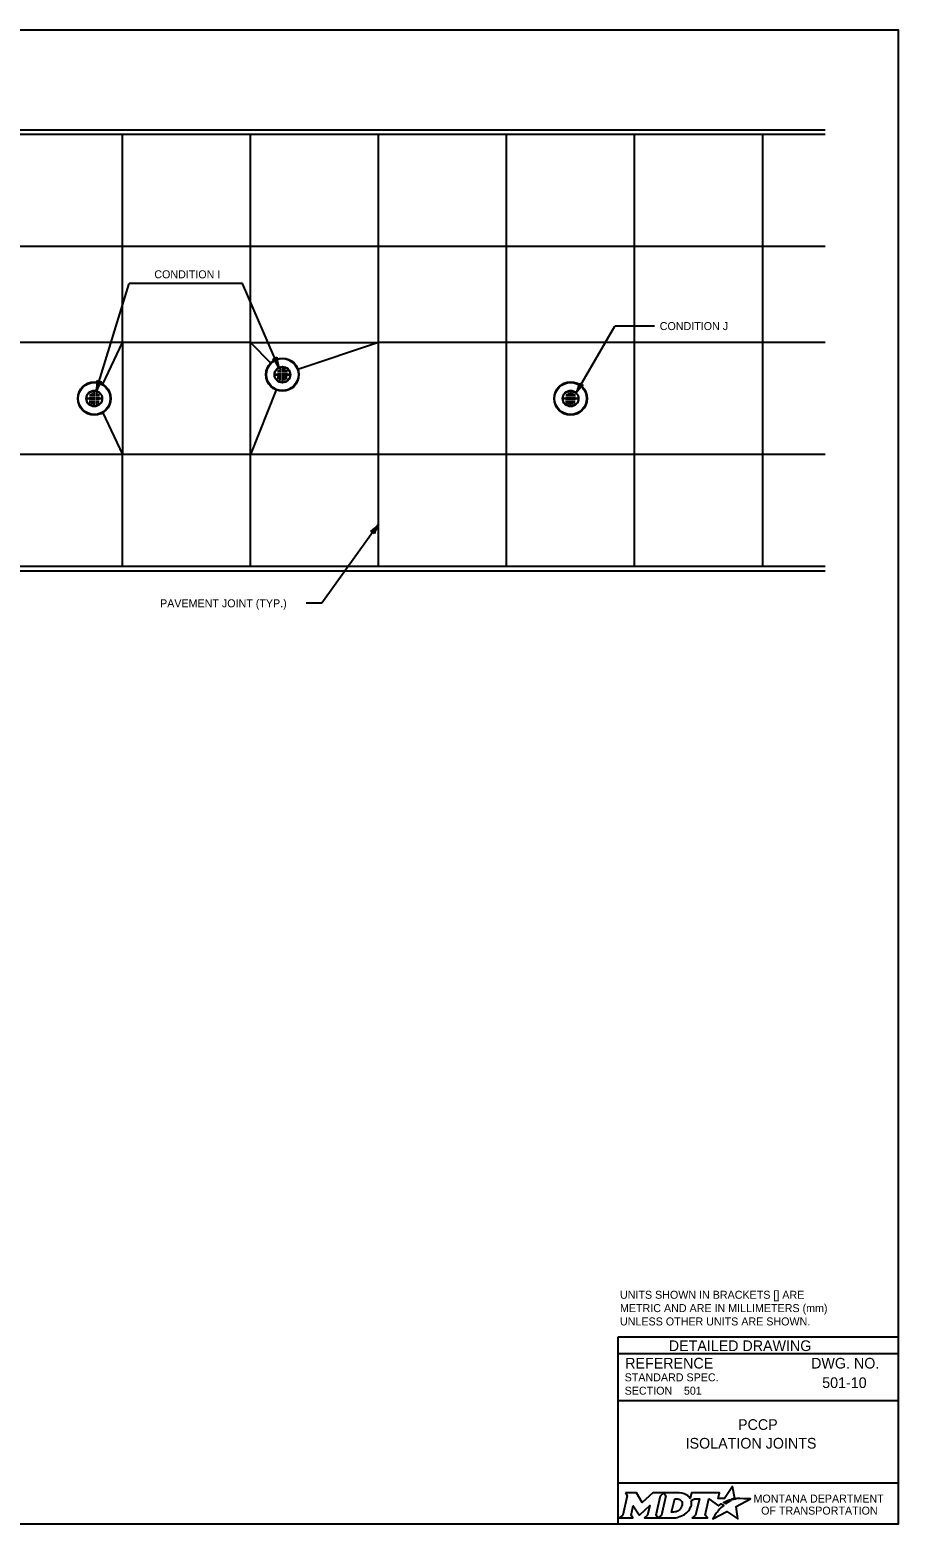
# Model space of a CAD drawing. Extents: x 49991.4 to 50029.7, y 49987.6 to 50011.4.
# Drawn here: x 50010.24 to 50016.75, y 49987.8 to 49999 of the extents above; entities that cross this region are included whole.
import ezdxf

# ---------------------------------------------------------------- set-up
doc = ezdxf.new("R2010")
doc.units = 0
for name, color, linetype in [('Default', 7, 'Continuous'), ('Level 1', 7, 'Continuous'), ('Level 2', 7, 'Continuous'), ('Level 3', 7, 'Continuous'), ('Level 5', 7, 'Continuous')]:
    doc.layers.add(name, color=color, linetype=linetype)

msp = doc.modelspace()

# ---------------------------------------------------------------- linework, layer by layer
at = {"layer": 'Default'}
for points in [[(50015.513, 49987.981), (50015.502, 49987.987), (50015.514, 49987.99), (50015.526, 49987.991), (50015.508, 49988.082), (50015.449, 49987.99), (50015.401, 49987.99), (50015.412, 49988.034), (50015.202, 49988.034), (50015.192, 49987.991), (50015.186, 49988)], [(50014.706, 49988.034), (50014.72, 49988.01), (50014.686, 49987.867), (50014.66, 49987.845), (50014.762, 49987.845), (50014.749, 49987.867), (50014.765, 49987.937), (50014.809, 49987.868), (50014.814, 49987.868), (50014.889, 49987.938), (50014.872, 49987.867), (50014.848, 49987.845), (50014.949, 49987.845), (50014.936, 49987.868), (50014.969, 49988.011)], [(50014.969, 49988.011), (50014.994, 49988.034), (50014.912, 49988.034), (50014.832, 49987.961), (50014.788, 49988.034), (50014.706, 49988.034)], [(50015.108, 49988.034), (50014.994, 49988.034), (50015.009, 49988.011), (50014.975, 49987.867), (50014.949, 49987.845), (50015.06, 49987.845)], [(50015.132, 49987.947), (50015.13, 49987.939), (50015.127, 49987.93), (50015.123, 49987.922), (50015.118, 49987.914), (50015.111, 49987.907), (50015.103, 49987.901), (50015.095, 49987.896), (50015.086, 49987.892), (50015.077, 49987.89), (50015.067, 49987.889), (50015.052, 49987.889), (50015.075, 49987.989), (50015.091, 49987.989), (50015.099, 49987.988), (50015.106, 49987.986), (50015.113, 49987.983), (50015.119, 49987.979), (50015.124, 49987.974), (50015.128, 49987.968), (50015.13, 49987.962), (50015.132, 49987.955), (50015.132, 49987.952), (50015.132, 49987.947)], [(50015.199, 49987.975), (50015.224, 49987.988), (50015.261, 49987.988), (50015.232, 49987.867), (50015.205, 49987.845), (50015.321, 49987.845), (50015.304, 49987.867), (50015.332, 49987.988), (50015.403, 49987.936), (50015.424, 49987.951), (50015.444, 49987.94)], [(50015.388, 49987.884), (50015.373, 49987.86), (50015.368, 49987.852), (50015.362, 49987.844), (50015.36, 49987.839), (50015.465, 49987.893), (50015.549, 49987.838), (50015.536, 49987.93), (50015.643, 49987.989), (50015.594, 49987.989), (50015.564, 49987.99), (50015.543, 49987.99), (50015.536, 49987.989), (50015.531, 49987.987), (50015.523, 49987.985), (50015.513, 49987.981)], [(50015.462, 49987.954), (50015.46, 49987.952), (50015.442, 49987.961), (50015.452, 49987.967), (50015.456, 49987.969), (50015.465, 49987.973), (50015.47, 49987.976), (50015.478, 49987.979), (50015.485, 49987.982), (50015.497, 49987.974), (50015.493, 49987.972), (50015.489, 49987.97), (50015.484, 49987.967), (50015.479, 49987.965), (50015.478, 49987.963), (50015.475, 49987.962), (50015.472, 49987.96), (50015.47, 49987.959), (50015.467, 49987.957), (50015.465, 49987.955), (50015.462, 49987.954)], [(50015.106, 49987.852), (50015.114, 49987.855), (50015.127, 49987.86), (50015.148, 49987.871)], [(50015.402, 49987.9), (50015.402, 49987.9)]]:
    msp.add_lwpolyline(points, dxfattribs=at)
for centre, radius, start, end in [((50015.131, 49987.955), 0.0709, 339.5329, 15.8582), ((50015.087, 49987.973), 0.118, 300.9103, 339.1383)]:
    msp.add_arc(centre, radius, start, end, dxfattribs=at)
for centre, major_axis, ratio, start_param, end_param in [((50015.106, 49987.986), (0.0834, -0.0037), 0.568097, 0.61298, 1.570796), ((50015.161, 49987.994), (0.0361, -0.0295), 0.469099, 1.225588, 1.570796), ((50015.06, 49987.993), (0, 0.148), 0.987302, 3.139398, 3.456847), ((50015.395, 49987.892), (-0.00694, -0.00806), 0.008222, 0, 3.137361), ((50015.412, 49987.911), (-0.0098, -0.0102), 0.016458, 3.141593, 6.279097), ((50015.433, 49987.93), (-0.0112, -0.0097), 0.021651, 3.157348, 6.283185)]:
    msp.add_ellipse(centre, major_axis=major_axis, ratio=ratio, start_param=start_param, end_param=end_param, dxfattribs=at)
at = {"layer": 'Level 1'}
for p, q in [((50016.203, 49998.248), (50005.815, 49998.248)), ((50016.203, 49998.216), (50005.815, 49998.216)), ((50010.935, 49996.656), (50010.935, 49998.216)), ((50011.895, 49996.656), (50011.895, 49998.216)), ((50012.855, 49997.376), (50012.855, 49998.216)), ((50013.815, 49994.976), (50013.815, 49998.216)), ((50014.775, 49994.976), (50014.775, 49998.216)), ((50015.735, 49994.976), (50015.735, 49998.216)), ((50016.203, 49997.376), (50000.003, 49997.376)), ((50012.855, 49994.976), (50012.855, 49997.376)), ((50011.895, 49996.656), (50000.003, 49996.656)), ((50010.787, 49996.343), (50010.935, 49996.656)), ((50010.935, 49996.656), (50010.935, 49995.816)), ((50011.895, 49996.656), (50012.046, 49996.503)), ((50011.895, 49995.816), (50011.895, 49996.656)), ((50011.895, 49996.656), (50012.855, 49996.656)), ((50012.855, 49996.656), (50012.251, 49996.454)), ((50016.203, 49996.656), (50012.855, 49996.656)), ((50012.118, 49996.46), (50012.118, 49996.43)), ((50012.134, 49996.463), (50012.134, 49996.43)), ((50012.149, 49996.46), (50012.149, 49996.43)), ((50012.088, 49996.423), (50012.088, 49996.407)), ((50012.103, 49996.451), (50012.103, 49996.43)), ((50012.103, 49996.426), (50012.103, 49996.404)), ((50012.103, 49996.379), (50012.103, 49996.4)), ((50012.118, 49996.426), (50012.118, 49996.404)), ((50012.118, 49996.37), (50012.118, 49996.4)), ((50012.134, 49996.426), (50012.134, 49996.404)), ((50012.134, 49996.367), (50012.134, 49996.4)), ((50012.149, 49996.426), (50012.149, 49996.404)), ((50012.149, 49996.37), (50012.149, 49996.4)), ((50012.164, 49996.451), (50012.164, 49996.43)), ((50012.164, 49996.426), (50012.164, 49996.404)), ((50012.164, 49996.379), (50012.164, 49996.4)), ((50012.18, 49996.423), (50012.18, 49996.407)), ((50010.678, 49996.244), (50010.678, 49996.228)), ((50010.694, 49996.272), (50010.694, 49996.251)), ((50010.694, 49996.247), (50010.694, 49996.225)), ((50010.709, 49996.281), (50010.709, 49996.251)), ((50010.709, 49996.247), (50010.709, 49996.225)), ((50010.724, 49996.284), (50010.724, 49996.251)), ((50010.724, 49996.247), (50010.724, 49996.225)), ((50010.74, 49996.281), (50010.74, 49996.251)), ((50010.74, 49996.247), (50010.74, 49996.225)), ((50010.755, 49996.272), (50010.755, 49996.251)), ((50010.755, 49996.247), (50010.755, 49996.225)), ((50010.77, 49996.244), (50010.77, 49996.228)), ((50012.088, 49996.3), (50011.895, 49995.816)), ((50014.249, 49996.244), (50014.249, 49996.228)), ((50014.264, 49996.272), (50014.264, 49996.251)), ((50014.264, 49996.247), (50014.264, 49996.225)), ((50014.279, 49996.281), (50014.279, 49996.251)), ((50014.279, 49996.247), (50014.279, 49996.225)), ((50014.295, 49996.284), (50014.295, 49996.251)), ((50014.295, 49996.247), (50014.295, 49996.225)), ((50014.31, 49996.281), (50014.31, 49996.251)), ((50014.31, 49996.247), (50014.31, 49996.225)), ((50014.325, 49996.272), (50014.325, 49996.251)), ((50014.325, 49996.247), (50014.325, 49996.225)), ((50014.34, 49996.244), (50014.34, 49996.228)), ((50010.694, 49996.199), (50010.694, 49996.22)), ((50010.709, 49996.19), (50010.709, 49996.22)), ((50010.724, 49996.188), (50010.724, 49996.22)), ((50010.74, 49996.19), (50010.74, 49996.22)), ((50010.755, 49996.199), (50010.755, 49996.22)), ((50010.787, 49996.129), (50010.935, 49995.816)), ((50014.264, 49996.199), (50014.264, 49996.22)), ((50014.279, 49996.19), (50014.279, 49996.22)), ((50014.295, 49996.188), (50014.295, 49996.22)), ((50014.31, 49996.19), (50014.31, 49996.22)), ((50014.325, 49996.199), (50014.325, 49996.22)), ((50016.203, 49995.816), (50007.331, 49995.816)), ((50010.935, 49994.976), (50010.935, 49995.816)), ((50011.895, 49994.976), (50011.895, 49995.816)), ((50016.203, 49994.943), (50004.326, 49994.943)), ((50016.203, 49994.976), (50004.331, 49994.976))]:
    msp.add_line(p, q, dxfattribs=at)
msp.add_lwpolyline([(49999.384, 49998.999), (50016.75, 49998.999), (50016.75, 49987.799), (49999.384, 49987.799)], close=True, dxfattribs=at)
for centre, radius in [((50012.134, 49996.415), 0.124), ((50012.134, 49996.415), 0.12), ((50012.134, 49996.415), 0.0602), ((50012.134, 49996.415), 0.0577), ((50010.724, 49996.236), 0.124), ((50010.724, 49996.236), 0.12), ((50014.295, 49996.236), 0.124), ((50014.295, 49996.236), 0.12), ((50010.724, 49996.236), 0.0602), ((50010.724, 49996.236), 0.0577), ((50014.295, 49996.236), 0.0602), ((50014.295, 49996.236), 0.0577)]:
    msp.add_circle(centre, radius, dxfattribs=at)
at = {"layer": 'Level 3'}
for p, q in [((50010.739, 49996.294), (50010.985, 49997.097)), ((50011.836, 49997.097), (50010.985, 49997.097)), ((50012.107, 49996.469), (50011.836, 49997.097)), ((50014.337, 49996.278), (50014.626, 49996.779)), ((50014.923, 49996.779), (50014.626, 49996.779)), ((50012.855, 49995.293), (50012.429, 49994.701)), ((50012.429, 49994.701), (50012.313, 49994.701))]:
    msp.add_line(p, q, dxfattribs=at)
for centre, radius, start, end in [((50012.056, 49996.587), 0.0548, 275.4865, 311.2089), ((50011.898, 49996.366), 0.233, 26.175, 45.4249), ((50012.315, 49996.549), 0.222, 180.8037, 200.9872), ((50010.513, 49996.351), 0.233, 345.8099, 5.0598), ((50010.949, 49996.22), 0.222, 140.4386, 160.6221), ((50010.777, 49996.417), 0.0548, 235.1214, 270.8438), ((50014.13, 49996.385), 0.233, 332.8273, 352.0772), ((50014.401, 49996.389), 0.0548, 222.1388, 257.8612), ((50014.525, 49996.159), 0.222, 127.456, 147.6395), ((50012.68, 49995.43), 0.222, 301.7368, 321.9204), ((50012.78, 49995.189), 0.0548, 36.4197, 72.142), ((50013.05, 49995.167), 0.233, 147.1081, 166.358)]:
    msp.add_arc(centre, radius, start, end, dxfattribs=at)
at = {"layer": 'Level 5'}
for p, q in [((50016.75, 49989.199), (50014.65, 49989.199)), ((50014.65, 49989.199), (50014.65, 49987.799)), ((50016.75, 49989.074), (50014.65, 49989.074)), ((50016.386, 49988.859), (50016.386, 49988.859)), ((50015.144, 49988.799), (50015.144, 49988.799)), ((50016.75, 49988.724), (50014.65, 49988.724)), ((50015.7, 49988.475), (50015.7, 49988.475)), ((50016.75, 49988.106), (50014.65, 49988.106))]:
    msp.add_line(p, q, dxfattribs=at)

# ---------------------------------------------------------------- texts
at = {"layer": 'Default'}
for s, p in [('MONTANA DEPARTMENT', (50015.666, 49987.96)), ('OF TRANSPORTATION', (50015.723, 49987.87))]:
    msp.add_text(s, height=0.06, dxfattribs=at).set_placement(p)
at = {"layer": 'Level 2'}
for s, p in [('CONDITION I', (50011.174, 49997.137)), ('PAVEMENT JOINT (TYP.)', (50011.217, 49994.671))]:
    msp.add_text(s, height=0.06, rotation=360, dxfattribs=at).set_placement(p)
for s, height, p in [('CONDITION J', 0.06, (50014.963, 49996.749)), ('UNITS SHOWN IN BRACKETS [] ARE ', 0.06, (50014.665, 49989.488)), ('METRIC AND ARE IN MILLIMETERS (mm) ', 0.06, (50014.665, 49989.388)), ('UNLESS OTHER UNITS ARE SHOWN.', 0.06, (50014.665, 49989.288)), ('501-10', 0.08, (50016.181, 49988.819)), ('501', 0.06, (50015.144, 49988.769)), ('PCCP', 0.08, (50015.55, 49988.505)), ('ISOLATION JOINTS', 0.08, (50015.157, 49988.365))]:
    msp.add_text(s, height=height, dxfattribs=at).set_placement(p)
at = {"layer": 'Level 5'}
for s, height, p in [('DETAILED DRAWING', 0.0799, (50015.031, 49989.096)), ('REFERENCE', 0.08, (50014.704, 49988.965)), ('DWG. NO.', 0.08, (50016.098, 49988.965)), ('STANDARD SPEC.', 0.06, (50014.7, 49988.869)), ('SECTION', 0.06, (50014.7, 49988.769))]:
    msp.add_text(s, height=height, dxfattribs=at).set_placement(p)

doc.saveas('drawing.dxf')
